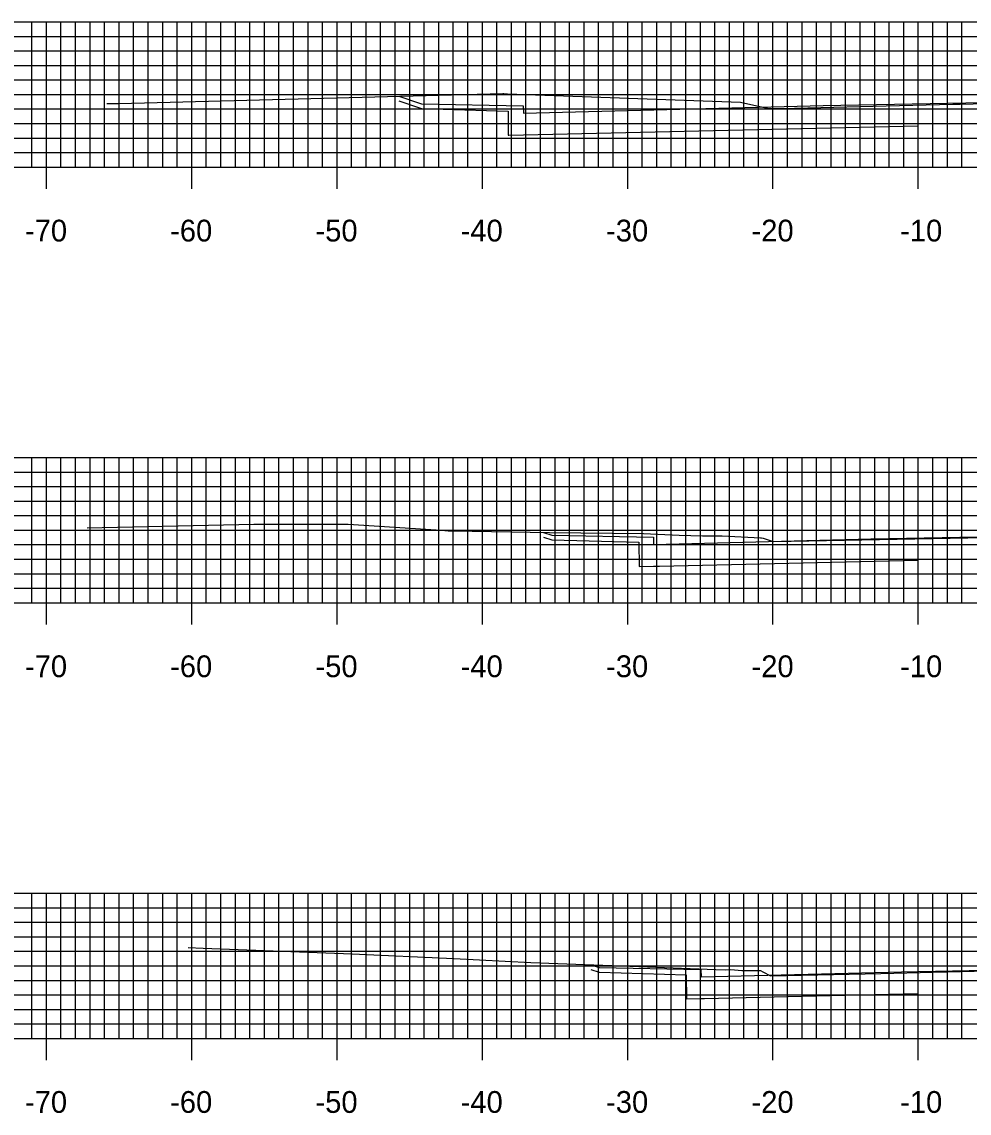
# Model space of a CAD drawing. Extents: x 40011 to 50684, y 49949 to 72236.
# Drawn here: x 41131.5 to 41196.7, y 71015.8 to 71091 of the extents above; entities that cross this region are included whole.
import ezdxf

# ---------------------------------------------------------------- set-up
doc = ezdxf.new("R2010")
doc.units = 0
for name, color, linetype in [('52', 7, 'Continuous'), ('53', 7, 'Continuous'), ('54', 7, 'Continuous'), ('55', 7, 'Continuous'), ('57', 7, 'Continuous'), ('58', 7, 'Continuous'), ('59', 7, 'Continuous')]:
    doc.layers.add(name, color=color, linetype=linetype)

msp = doc.modelspace()

# ---------------------------------------------------------------- linework, layer by layer
at = {"layer": '52'}
for p, q in [((41063.216, 71080.983), (41343.216, 71080.983)), ((41133.216, 71079.483), (41133.216, 71080.983)), ((41143.216, 71079.483), (41143.216, 71080.983)), ((41153.216, 71079.483), (41153.216, 71080.983)), ((41163.216, 71079.483), (41163.216, 71080.983)), ((41173.216, 71079.483), (41173.216, 71080.983)), ((41183.216, 71079.483), (41183.216, 71080.983)), ((41193.216, 71079.483), (41193.216, 71080.983)), ((41063.216, 71050.983), (41343.216, 71050.983)), ((41133.216, 71049.483), (41133.216, 71050.983)), ((41143.216, 71049.483), (41143.216, 71050.983)), ((41153.216, 71049.483), (41153.216, 71050.983)), ((41163.216, 71049.483), (41163.216, 71050.983)), ((41173.216, 71049.483), (41173.216, 71050.983)), ((41183.216, 71049.483), (41183.216, 71050.983)), ((41193.216, 71049.483), (41193.216, 71050.983)), ((41063.216, 71020.983), (41343.216, 71020.983)), ((41133.216, 71019.483), (41133.216, 71020.983)), ((41143.216, 71019.483), (41143.216, 71020.983)), ((41153.216, 71019.483), (41153.216, 71020.983)), ((41163.216, 71019.483), (41163.216, 71020.983)), ((41173.216, 71019.483), (41173.216, 71020.983)), ((41183.216, 71019.483), (41183.216, 71020.983)), ((41193.216, 71019.483), (41193.216, 71020.983))]:
    msp.add_line(p, q, dxfattribs=at)
at = {"layer": '53'}
for p, q in [((41063.216, 71089.983), (41343.216, 71089.983)), ((41063.216, 71088.983), (41343.216, 71088.983)), ((41063.216, 71087.983), (41343.216, 71087.983)), ((41063.216, 71086.983), (41343.216, 71086.983)), ((41063.216, 71085.983), (41343.216, 71085.983)), ((41063.216, 71084.983), (41343.216, 71084.983)), ((41063.216, 71083.983), (41343.216, 71083.983)), ((41063.216, 71082.983), (41343.216, 71082.983)), ((41063.216, 71081.983), (41343.216, 71081.983)), ((41063.216, 71059.983), (41343.216, 71059.983)), ((41063.216, 71058.983), (41343.216, 71058.983)), ((41063.216, 71057.983), (41343.216, 71057.983)), ((41063.216, 71056.983), (41343.216, 71056.983)), ((41063.216, 71055.983), (41343.216, 71055.983)), ((41063.216, 71054.983), (41343.216, 71054.983)), ((41063.216, 71053.983), (41343.216, 71053.983)), ((41063.216, 71052.983), (41343.216, 71052.983)), ((41063.216, 71051.983), (41343.216, 71051.983)), ((41063.216, 71029.983), (41343.216, 71029.983)), ((41063.216, 71028.983), (41343.216, 71028.983)), ((41063.216, 71027.983), (41343.216, 71027.983)), ((41063.216, 71026.983), (41343.216, 71026.983)), ((41063.216, 71025.983), (41343.216, 71025.983)), ((41063.216, 71024.983), (41343.216, 71024.983)), ((41063.216, 71023.983), (41343.216, 71023.983)), ((41063.216, 71022.983), (41343.216, 71022.983)), ((41063.216, 71021.983), (41343.216, 71021.983))]:
    msp.add_line(p, q, dxfattribs=at)
at = {"layer": '54'}
for p, q in [((41132.216, 71080.983), (41132.216, 71090.983)), ((41134.216, 71080.983), (41134.216, 71090.983)), ((41135.216, 71080.983), (41135.216, 71090.983)), ((41136.216, 71080.983), (41136.216, 71090.983)), ((41137.216, 71080.983), (41137.216, 71090.983)), ((41138.216, 71080.983), (41138.216, 71090.983)), ((41139.216, 71080.983), (41139.216, 71090.983)), ((41140.216, 71080.983), (41140.216, 71090.983)), ((41141.216, 71080.983), (41141.216, 71090.983)), ((41142.216, 71080.983), (41142.216, 71090.983)), ((41144.216, 71080.983), (41144.216, 71090.983)), ((41145.216, 71080.983), (41145.216, 71090.983)), ((41146.216, 71080.983), (41146.216, 71090.983)), ((41147.216, 71080.983), (41147.216, 71090.983)), ((41148.216, 71080.983), (41148.216, 71090.983)), ((41149.216, 71080.983), (41149.216, 71090.983)), ((41150.216, 71080.983), (41150.216, 71090.983)), ((41151.216, 71080.983), (41151.216, 71090.983)), ((41152.216, 71080.983), (41152.216, 71090.983)), ((41154.216, 71080.983), (41154.216, 71090.983)), ((41155.216, 71080.983), (41155.216, 71090.983)), ((41156.216, 71080.983), (41156.216, 71090.983)), ((41157.216, 71080.983), (41157.216, 71090.983)), ((41158.216, 71080.983), (41158.216, 71090.983)), ((41159.216, 71080.983), (41159.216, 71090.983)), ((41160.216, 71080.983), (41160.216, 71090.983)), ((41161.216, 71080.983), (41161.216, 71090.983)), ((41162.216, 71080.983), (41162.216, 71090.983)), ((41164.216, 71080.983), (41164.216, 71090.983)), ((41165.216, 71080.983), (41165.216, 71090.983)), ((41166.216, 71080.983), (41166.216, 71090.983)), ((41167.216, 71080.983), (41167.216, 71090.983)), ((41168.216, 71080.983), (41168.216, 71090.983)), ((41169.216, 71080.983), (41169.216, 71090.983)), ((41170.216, 71080.983), (41170.216, 71090.983)), ((41171.216, 71080.983), (41171.216, 71090.983)), ((41172.216, 71080.983), (41172.216, 71090.983)), ((41174.216, 71080.983), (41174.216, 71090.983)), ((41175.216, 71080.983), (41175.216, 71090.983)), ((41176.216, 71080.983), (41176.216, 71090.983)), ((41177.216, 71080.983), (41177.216, 71090.983)), ((41178.216, 71080.983), (41178.216, 71090.983)), ((41179.216, 71080.983), (41179.216, 71090.983)), ((41180.216, 71080.983), (41180.216, 71090.983)), ((41181.216, 71080.983), (41181.216, 71090.983)), ((41182.216, 71080.983), (41182.216, 71090.983)), ((41184.216, 71080.983), (41184.216, 71090.983)), ((41185.216, 71080.983), (41185.216, 71090.983)), ((41186.216, 71080.983), (41186.216, 71090.983)), ((41187.216, 71080.983), (41187.216, 71090.983)), ((41188.216, 71080.983), (41188.216, 71090.983)), ((41189.216, 71080.983), (41189.216, 71090.983)), ((41190.216, 71080.983), (41190.216, 71090.983)), ((41191.216, 71080.983), (41191.216, 71090.983)), ((41192.216, 71080.983), (41192.216, 71090.983)), ((41194.216, 71080.983), (41194.216, 71090.983)), ((41195.216, 71080.983), (41195.216, 71090.983)), ((41196.216, 71080.983), (41196.216, 71090.983)), ((41132.216, 71050.983), (41132.216, 71060.983)), ((41134.216, 71050.983), (41134.216, 71060.983)), ((41135.216, 71050.983), (41135.216, 71060.983)), ((41136.216, 71050.983), (41136.216, 71060.983)), ((41137.216, 71050.983), (41137.216, 71060.983)), ((41138.216, 71050.983), (41138.216, 71060.983)), ((41139.216, 71050.983), (41139.216, 71060.983)), ((41140.216, 71050.983), (41140.216, 71060.983)), ((41141.216, 71050.983), (41141.216, 71060.983)), ((41142.216, 71050.983), (41142.216, 71060.983)), ((41144.216, 71050.983), (41144.216, 71060.983)), ((41145.216, 71050.983), (41145.216, 71060.983)), ((41146.216, 71050.983), (41146.216, 71060.983)), ((41147.216, 71050.983), (41147.216, 71060.983)), ((41148.216, 71050.983), (41148.216, 71060.983)), ((41149.216, 71050.983), (41149.216, 71060.983)), ((41150.216, 71050.983), (41150.216, 71060.983)), ((41151.216, 71050.983), (41151.216, 71060.983)), ((41152.216, 71050.983), (41152.216, 71060.983)), ((41154.216, 71050.983), (41154.216, 71060.983)), ((41155.216, 71050.983), (41155.216, 71060.983)), ((41156.216, 71050.983), (41156.216, 71060.983)), ((41157.216, 71050.983), (41157.216, 71060.983)), ((41158.216, 71050.983), (41158.216, 71060.983)), ((41159.216, 71050.983), (41159.216, 71060.983)), ((41160.216, 71050.983), (41160.216, 71060.983)), ((41161.216, 71050.983), (41161.216, 71060.983)), ((41162.216, 71050.983), (41162.216, 71060.983)), ((41164.216, 71050.983), (41164.216, 71060.983)), ((41165.216, 71050.983), (41165.216, 71060.983)), ((41166.216, 71050.983), (41166.216, 71060.983)), ((41167.216, 71050.983), (41167.216, 71060.983)), ((41168.216, 71050.983), (41168.216, 71060.983)), ((41169.216, 71050.983), (41169.216, 71060.983)), ((41170.216, 71050.983), (41170.216, 71060.983)), ((41171.216, 71050.983), (41171.216, 71060.983)), ((41172.216, 71050.983), (41172.216, 71060.983)), ((41174.216, 71050.983), (41174.216, 71060.983)), ((41175.216, 71050.983), (41175.216, 71060.983)), ((41176.216, 71050.983), (41176.216, 71060.983)), ((41177.216, 71050.983), (41177.216, 71060.983)), ((41178.216, 71050.983), (41178.216, 71060.983)), ((41179.216, 71050.983), (41179.216, 71060.983)), ((41180.216, 71050.983), (41180.216, 71060.983)), ((41181.216, 71050.983), (41181.216, 71060.983)), ((41182.216, 71050.983), (41182.216, 71060.983)), ((41184.216, 71050.983), (41184.216, 71060.983)), ((41185.216, 71050.983), (41185.216, 71060.983)), ((41186.216, 71050.983), (41186.216, 71060.983)), ((41187.216, 71050.983), (41187.216, 71060.983)), ((41188.216, 71050.983), (41188.216, 71060.983)), ((41189.216, 71050.983), (41189.216, 71060.983)), ((41190.216, 71050.983), (41190.216, 71060.983)), ((41191.216, 71050.983), (41191.216, 71060.983)), ((41192.216, 71050.983), (41192.216, 71060.983)), ((41194.216, 71050.983), (41194.216, 71060.983)), ((41195.216, 71050.983), (41195.216, 71060.983)), ((41196.216, 71050.983), (41196.216, 71060.983)), ((41132.216, 71020.983), (41132.216, 71030.983)), ((41134.216, 71020.983), (41134.216, 71030.983)), ((41135.216, 71020.983), (41135.216, 71030.983)), ((41136.216, 71020.983), (41136.216, 71030.983)), ((41137.216, 71020.983), (41137.216, 71030.983)), ((41138.216, 71020.983), (41138.216, 71030.983)), ((41139.216, 71020.983), (41139.216, 71030.983)), ((41140.216, 71020.983), (41140.216, 71030.983)), ((41141.216, 71020.983), (41141.216, 71030.983)), ((41142.216, 71020.983), (41142.216, 71030.983)), ((41144.216, 71020.983), (41144.216, 71030.983)), ((41145.216, 71020.983), (41145.216, 71030.983)), ((41146.216, 71020.983), (41146.216, 71030.983)), ((41147.216, 71020.983), (41147.216, 71030.983)), ((41148.216, 71020.983), (41148.216, 71030.983)), ((41149.216, 71020.983), (41149.216, 71030.983)), ((41150.216, 71020.983), (41150.216, 71030.983)), ((41151.216, 71020.983), (41151.216, 71030.983)), ((41152.216, 71020.983), (41152.216, 71030.983)), ((41154.216, 71020.983), (41154.216, 71030.983)), ((41155.216, 71020.983), (41155.216, 71030.983)), ((41156.216, 71020.983), (41156.216, 71030.983)), ((41157.216, 71020.983), (41157.216, 71030.983)), ((41158.216, 71020.983), (41158.216, 71030.983)), ((41159.216, 71020.983), (41159.216, 71030.983)), ((41160.216, 71020.983), (41160.216, 71030.983)), ((41161.216, 71020.983), (41161.216, 71030.983)), ((41162.216, 71020.983), (41162.216, 71030.983)), ((41164.216, 71020.983), (41164.216, 71030.983)), ((41165.216, 71020.983), (41165.216, 71030.983)), ((41166.216, 71020.983), (41166.216, 71030.983)), ((41167.216, 71020.983), (41167.216, 71030.983)), ((41168.216, 71020.983), (41168.216, 71030.983)), ((41169.216, 71020.983), (41169.216, 71030.983)), ((41170.216, 71020.983), (41170.216, 71030.983)), ((41171.216, 71020.983), (41171.216, 71030.983)), ((41172.216, 71020.983), (41172.216, 71030.983)), ((41174.216, 71020.983), (41174.216, 71030.983)), ((41175.216, 71020.983), (41175.216, 71030.983)), ((41176.216, 71020.983), (41176.216, 71030.983)), ((41177.216, 71020.983), (41177.216, 71030.983)), ((41178.216, 71020.983), (41178.216, 71030.983)), ((41179.216, 71020.983), (41179.216, 71030.983)), ((41180.216, 71020.983), (41180.216, 71030.983)), ((41181.216, 71020.983), (41181.216, 71030.983)), ((41182.216, 71020.983), (41182.216, 71030.983)), ((41184.216, 71020.983), (41184.216, 71030.983)), ((41185.216, 71020.983), (41185.216, 71030.983)), ((41186.216, 71020.983), (41186.216, 71030.983)), ((41187.216, 71020.983), (41187.216, 71030.983)), ((41188.216, 71020.983), (41188.216, 71030.983)), ((41189.216, 71020.983), (41189.216, 71030.983)), ((41190.216, 71020.983), (41190.216, 71030.983)), ((41191.216, 71020.983), (41191.216, 71030.983)), ((41192.216, 71020.983), (41192.216, 71030.983)), ((41194.216, 71020.983), (41194.216, 71030.983)), ((41195.216, 71020.983), (41195.216, 71030.983)), ((41196.216, 71020.983), (41196.216, 71030.983))]:
    msp.add_line(p, q, dxfattribs=at)
at = {"layer": '55'}
for p, q in [((41063.216, 71090.983), (41343.216, 71090.983)), ((41133.216, 71080.983), (41133.216, 71090.983)), ((41143.216, 71080.983), (41143.216, 71090.983)), ((41153.216, 71080.983), (41153.216, 71090.983)), ((41163.216, 71080.983), (41163.216, 71090.983)), ((41173.216, 71080.983), (41173.216, 71090.983)), ((41183.216, 71080.983), (41183.216, 71090.983)), ((41193.216, 71080.983), (41193.216, 71090.983)), ((41063.216, 71080.983), (41343.216, 71080.983)), ((41063.216, 71060.983), (41343.216, 71060.983)), ((41133.216, 71050.983), (41133.216, 71060.983)), ((41143.216, 71050.983), (41143.216, 71060.983)), ((41153.216, 71050.983), (41153.216, 71060.983)), ((41163.216, 71050.983), (41163.216, 71060.983)), ((41173.216, 71050.983), (41173.216, 71060.983)), ((41183.216, 71050.983), (41183.216, 71060.983)), ((41193.216, 71050.983), (41193.216, 71060.983)), ((41063.216, 71050.983), (41343.216, 71050.983)), ((41063.216, 71030.983), (41343.216, 71030.983)), ((41133.216, 71020.983), (41133.216, 71030.983)), ((41143.216, 71020.983), (41143.216, 71030.983)), ((41153.216, 71020.983), (41153.216, 71030.983)), ((41163.216, 71020.983), (41163.216, 71030.983)), ((41173.216, 71020.983), (41173.216, 71030.983)), ((41183.216, 71020.983), (41183.216, 71030.983)), ((41193.216, 71020.983), (41193.216, 71030.983)), ((41063.216, 71020.983), (41343.216, 71020.983))]:
    msp.add_line(p, q, dxfattribs=at)
at = {"layer": '57'}
for points in [[(41137.379, 71085.349), (41138.193, 71085.358), (41164.627, 71086.052), (41164.685, 71086.051), (41164.953, 71086.035), (41180.972, 71085.444), (41182.927, 71085.006), (41183.806, 71085.025), (41191.013, 71085.201), (41195.589, 71085.312), (41196.096, 71085.324), (41203.299, 71085.499)], [(41136.012, 71056.137), (41147.494, 71056.405), (41153.97, 71056.383), (41160.038, 71055.995), (41160.626, 71055.953), (41160.75, 71055.948), (41160.859, 71055.944), (41160.963, 71055.945), (41161.069, 71055.945), (41161.18, 71055.945), (41161.188, 71055.945), (41167.828, 71055.822), (41174.295, 71055.751), (41176.759, 71055.627), (41178.367, 71055.598), (41179.708, 71055.592), (41182.354, 71055.449), (41182.426, 71055.444), (41182.529, 71055.44), (41183.239, 71055.204), (41183.25, 71055.2), (41202.698, 71055.577)], [(41142.968, 71027.251), (41144.003, 71027.192), (41154.253, 71026.798), (41161.259, 71026.491), (41166.542, 71026.204), (41173.982, 71025.946), (41179.285, 71025.739), (41179.938, 71025.711), (41180.312, 71025.719), (41181.074, 71025.668), (41181.272, 71025.666), (41182.367, 71025.652), (41182.513, 71025.573), (41183.046, 71025.295), (41190.648, 71025.461), (41194.229, 71025.555), (41201.731, 71025.73)]]:
    msp.add_lwpolyline(points, dxfattribs=at)
at = {"layer": '58'}
for points in [[(41157.456, 71085.534), (41159.032, 71085.009), (41164.986, 71084.838), (41164.986, 71084.789), (41164.995, 71083.169), (41165.026, 71083.17), (41166.041, 71083.197), (41166.045, 71083.197), (41193.216, 71083.829)], [(41167.429, 71055.499), (41167.986, 71055.314), (41167.998, 71055.314), (41173.985, 71055.145), (41173.985, 71055.134), (41173.995, 71053.475), (41174.996, 71053.502), (41174.998, 71053.502), (41175.001, 71053.502), (41175.412, 71053.512), (41193.217, 71053.919)], [(41170.683, 71025.73), (41171.253, 71025.54), (41171.28, 71025.539), (41177.252, 71025.371), (41177.252, 71025.36), (41177.262, 71023.701), (41177.269, 71023.701), (41178.263, 71023.729), (41178.501, 71023.735), (41187.124, 71023.934), (41193.216, 71024.075)]]:
    msp.add_lwpolyline(points, dxfattribs=at)
at = {"layer": '59'}
for points in [[(41157.456, 71085.864), (41159.032, 71085.339), (41166.032, 71085.199), (41166.042, 71084.699), (41186.663, 71085.214), (41197.701, 71085.435), (41200.707, 71085.495), (41200.848, 71085.998), (41203.216, 71085.546), (41203.216, 71085.546), (41204.575, 71086.021), (41204.716, 71085.523), (41208.717, 71085.463), (41219.717, 71085.243), (41230.703, 71084.968), (41230.713, 71085.468), (41237.713, 71085.608), (41240.37, 71086.494)], [(41167.43, 71055.829), (41167.986, 71055.644), (41174.986, 71055.504), (41174.996, 71055.004), (41189.959, 71055.378), (41200.989, 71055.599), (41203.216, 71055.643), (41203.216, 71055.643), (41205.707, 71055.606), (41217.517, 71055.37), (41227.508, 71055.12), (41227.518, 71055.62), (41234.518, 71055.76), (41234.544, 71055.769)], [(41170.683, 71026.06), (41171.254, 71025.87), (41178.254, 71025.73), (41178.264, 71025.23), (41192.05, 71025.575), (41200.216, 71025.738), (41203.216, 71025.798), (41203.216, 71025.798), (41208.716, 71025.716), (41215.317, 71025.584), (41224.314, 71025.359), (41224.324, 71025.859), (41231.324, 71025.999), (41232.654, 71025.555)]]:
    msp.add_lwpolyline(points, dxfattribs=at)

# ---------------------------------------------------------------- texts
at = {"layer": '52'}
for s, p in [('-70', (41131.737, 71075.858)), ('-60', (41141.726, 71075.858)), ('-50', (41151.73, 71075.858)), ('-40', (41161.72, 71075.858)), ('-30', (41171.729, 71075.858)), ('-20', (41181.737, 71075.858)), ('-10', (41191.965, 71075.858)), ('-70', (41131.737, 71045.858)), ('-60', (41141.726, 71045.858)), ('-50', (41151.73, 71045.858)), ('-40', (41161.72, 71045.858)), ('-30', (41171.729, 71045.858)), ('-20', (41181.737, 71045.858)), ('-10', (41191.965, 71045.858)), ('-70', (41131.737, 71015.858)), ('-60', (41141.726, 71015.858)), ('-50', (41151.73, 71015.858)), ('-40', (41161.72, 71015.858)), ('-30', (41171.729, 71015.858)), ('-20', (41181.737, 71015.858)), ('-10', (41191.965, 71015.858))]:
    msp.add_text(s, height=1.5, dxfattribs=at).set_placement(p)

doc.saveas('drawing.dxf')
